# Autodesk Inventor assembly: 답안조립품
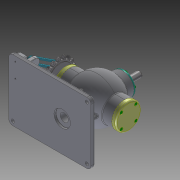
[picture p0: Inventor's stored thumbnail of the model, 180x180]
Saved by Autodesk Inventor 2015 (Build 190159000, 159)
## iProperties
Created: 2017-07
Part Number: 답안조립품
Document SubType Name: Assembly
Designer: owner
Author: owner
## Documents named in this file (20)
- C:\Users\owner\Desktop\370707V1012\답안조립품.iam
- C:\Users\owner\Desktop\370707V1012\본체.ipt
- C:\Users\owner\Desktop\370707V1012\축.ipt
- C:\Users\owner\Desktop\370707V1012\키 3 x 3 x 12.ipt
- C:\Users\owner\Desktop\370707V1012\베어링 6202.ipt
- C:\Users\owner\Desktop\370707V1012\뒤커버.ipt
- C:\Users\owner\Desktop\370707V1012\볼트 M4x12.ipt
- C:\Users\owner\Desktop\370707V1012\앞커버.ipt
- C:\Users\owner\Desktop\370707V1012\오일실.ipt
- C:\Users\owner\Desktop\370707V1012\스프로킷.ipt
- C:\Users\owner\Desktop\370707V1012\너트 M8x1.ipt
- C:\Users\owner\Desktop\370707V1012\와셔 8x17.ipt
- C:\Users\owner\Desktop\370707V1012\고정핀.ipt
- C:\Users\owner\Desktop\370707V1012\연결대.ipt
- C:\Users\owner\Desktop\370707V1012\둥근머리 볼트 M4x8.ipt
- C:\Users\owner\Desktop\370707V1012\와셔 ISO 7093 A.ipt
- C:\Users\owner\Desktop\370707V1012\본체커버.ipt
- C:\Users\owner\Desktop\370707V1012\슬라이드 커버.ipt
- C:\Users\owner\Desktop\370707V1012\슬라이드.ipt
- C:\Users\owner\Desktop\370707V1012\스프링.ipt
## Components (1 placed, 1 different names)
1. 고정핀:1
